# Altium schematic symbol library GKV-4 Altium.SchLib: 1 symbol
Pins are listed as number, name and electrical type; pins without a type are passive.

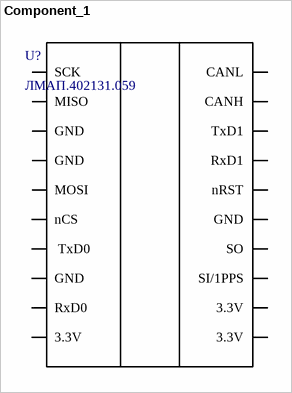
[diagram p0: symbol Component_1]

## Component_1
designator U?, comment ЛМАП.402131.059
Инерциальный модуль на основе микроконтроллера STM32F767VGH6 и датчиков: XV7021BB, ADXL357BEZ, MMC5983MA, LPS27HHTWTR.; Manufacturer: ЛМП; Код: БП-00006945; Наименование: Модуль инерциальный ГКВ-4-415021 ЛМАП.402131.059
footprint Модуль инерциальный ГКВ-4-415021 ЛМАП.402131.059
pins: 1 SCK, 2 MISO, 3 GND, 4 GND, 5 MOSI, 6 nCS, 7  TxD0, 8 GND, 9 RxD0, 10 3.3V, 11 3.3V, 12 3.3V, 13 SI/1PPS, 14 SO, 15 GND, 16 nRST, 17 RxD1, 18 TxD1, 19 CANH, 20 CANL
